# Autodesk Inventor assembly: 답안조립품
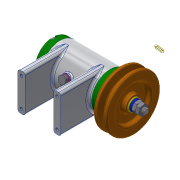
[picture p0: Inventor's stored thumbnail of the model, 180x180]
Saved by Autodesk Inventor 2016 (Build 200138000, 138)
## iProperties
Created: 2020-07
Part Number: 답안조립품
Document SubType Name: Assembly
Designer: user
Author: user
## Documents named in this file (15)
- C:\Users\user\Desktop\700706V1004\답안조립품.iam
- C:\Users\user\Desktop\700706V1004\본체.ipt
- C:\Users\user\Desktop\700706V1004\베어링 6002.ipt
- C:\Users\user\Desktop\700706V1004\축.ipt
- C:\Users\user\Desktop\700706V1004\앞커버.ipt
- C:\Users\user\Desktop\700706V1004\뒤커버.ipt
- C:\Users\user\Desktop\700706V1004\볼트 M4x12.ipt
- C:\Users\user\Desktop\700706V1004\오일 실 15 25 7.ipt
- C:\Users\user\Desktop\700706V1004\키 3x3x12.ipt
- C:\Users\user\Desktop\700706V1004\V벨트풀리.ipt
- C:\Users\user\Desktop\700706V1004\와셔 8x17.ipt
- C:\Users\user\Desktop\700706V1004\스프링와셔 8.ipt
- C:\Users\user\Desktop\700706V1004\너트 M8.ipt
- C:\Users\user\Desktop\700706V1004\와셔 6x11.5.ipt
- C:\Users\user\Desktop\700706V1004\볼트 M6x8.ipt
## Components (1 placed, 1 different names)
1. V벨트풀리:1
